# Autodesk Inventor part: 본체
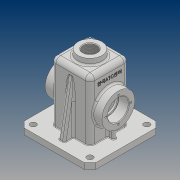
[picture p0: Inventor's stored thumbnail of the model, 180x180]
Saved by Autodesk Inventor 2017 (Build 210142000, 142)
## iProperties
Part Number: 본체
Material: 일반
Document SubType Name: Modeling
Designer: 20
Density: 1 g/cm^3
Appearance: 기본값
Author: 20
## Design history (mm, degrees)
sketch "스케치1"
  geometry: L1 (-32.5, -32.5)-(32.5, -32.5); L2 (32.5, -32.5)-(32.5, 32.5); L3 (32.5, 32.5)-(-32.5, 32.5); L4 (-32.5, 32.5)-(-32.5, -32.5); L5 (-32.5, -32.5)-(32.5, 32.5); L6 (32.5, -32.5)-(-32.5, 32.5); 1 further point
  constraints: 12 end point, 2 midpoint, 2 parallel, 1 horizontal, 1 perpendicular
  dimensions: "d0" = 65 distance of L3.end L2.end; "d1" = 65 distance of L2.end L1.end
extrude "돌출1" new body sketch "스케치1" distance "d2" = 110; taper "d3" = 0 deg
sketch "스케치2"
  geometry: L1 (27.5, 27.5)-(-27.5, 27.5); L2 (-27.5, 27.5)-(-27.5, -27.5); L3 (-27.5, -27.5)-(27.5, -27.5); L4 (27.5, -27.5)-(27.5, 27.5); L5 (27.5, 27.5)-(-27.5, -27.5); L6 (-27.5, 27.5)-(27.5, -27.5); 1 further point
  constraints: 12 end point, 2 midpoint, 2 parallel, 1 horizontal, 1 perpendicular
  dimensions: "d4" = 55 distance of L3.end L2.end; "d5" = 55 distance of L2.end L1.end
extrude "돌출2" cut sketch "스케치2" distance "d6" = 105; taper "d7" = 0 deg
sketch "스케치3"
  geometry: L1 (60, -60)-(-60, -60); L2 (-60, -60)-(-60, 60); L3 (-60, 60)-(60, 60); L4 (60, 60)-(60, -60); L5 (60, -60)-(-60, 60); L6 (-60, -60)-(60, 60); L7 (27.5, -27.5)-(-27.5, -27.5) reference; L8 (-27.5, -27.5)-(-27.5, 27.5) reference; L9 (-27.5, 27.5)-(27.5, 27.5) reference; L10 (27.5, 27.5)-(27.5, -27.5) reference; 1 further point
  constraints: 12 end point, 2 midpoint, 2 parallel, 1 horizontal, 1 perpendicular
  dimensions: "d8" = 120 distance of L2.end L3.end; "d9" = 120 distance of L1.end L2.end
extrude "돌출3" join sketch "스케치3" distance "d10" = 10; taper "d11" = 0 deg
sketch "스케치4"
  geometry: C1 r 20 at (0, 0); 1 further point
  constraints: 1 centre point, 1 coincident
  dimensions: "d12" = 40 diameter of C1
extrude "돌출4" join sketch "스케치4" distance "d13" = 10; taper "d14" = 0 deg
feature "면 기울기2" dims angle "d16" = 5 deg
sketch "스케치5"
  geometry: L1 (110, -27.5)-(110, 92.5) reference; C1 r 27.5 at (55, 32.5); 2 further points
  constraints: 1 centre point, 1 horizontal alignment, 1 midpoint
  dimensions: "d17" = 55 diameter of C1; "d92" = 55 distance from line of L1 C1.centre
extrude "돌출5" join sketch "스케치5" distance "d18" = 15; taper "d19" = 0 deg
sketch "스케치6"
  geometry: C1 r 27.5 at (0, 0) reference; C2 r 17.5 at (0, 0); 1 further point
  constraints: 1 centre point, 1 coincident
  dimensions: "d20" = 35 diameter of C2
extrude "돌출6" cut sketch "스케치6" distance "d21" = 17; taper "d22" = 0 deg
sketch "스케치7"
  geometry: C1 r 17.5 at (0, 0) reference; C2 r 15 at (0, 0); 1 further point
  constraints: 1 centre point, 1 coincident
  dimensions: "d23" = 30 diameter of C2
extrude "돌출7" cut sketch "스케치7" distance "d24" = 3; taper "d25" = 0 deg
fillet "모깎기3" dims "d28" = 3
fillet "모깎기4" dims "d29" = 3
sketch "스케치8" dims "d30" = 42
  geometry: C1 r 27.5 at (0, 0) reference; 3 further points
  constraints: 2 horizontal alignment, 1 coincident, 2 other
hole "구멍1" sketch "스케치8" at (-21, 0) diameter "d31" = 3.242; stored, may be unused: countersink angle "d35" = 90 deg, drill point angle "d37" = 118 deg; dims "d32" = 8, "d33" = 4, "d34" = 2, "d36" = 10
hole "구멍2" diameter "d43" = 22.835; stored, may be unused: countersink angle "d47" = 90 deg, drill point angle "d49" = 118 deg; dims "d41" = 10, "d42" = 10, "d44" = 50, "d45" = 4, "d46" = 2, "d48" = 15
sketch "스케치9"
  geometry: L1 (-60, 10)-(60, 10) reference; L2 (-42.5, 10)-(-42.5, 25); L3 (-27.5, 0)-(-27.5, 102) reference; 1 further point
  constraints: 2 end point, 1 point on line, 1 vertical
  dimensions: "d50" = 15 distance between parallel lines of L2 L3; "d51" = 15 distance of L2.start L2.end
feature "리브1" sketch "스케치9" dims "d52" = 1, "d53" = 6, "d54" = 0, "d55" = 0, "d56" = 1, "d57" = 1
sketch "스케치10"
  geometry: L1 (48, 10)-(37.42, 70); L2 (60, 0)-(60, 10) reference; L3 (60, 10)-(-60, 10) reference; 1 further point
  constraints: 2 end point, 1 point on line
  dimensions: "d58" = 10 deg angle of L2 L1; "d59" = 12 distance from line of L2 L1.start; "d60" = 60 vertical distance of L1.start L1.end
feature "리브2" sketch "스케치10" dims "d61" = 1, "d62" = 10, "d63" = 0, "d64" = 0, "d65" = 1, "d66" = 1
node "작업 평면1"
chamfer "모따기1" distance "d72" = 10; stored, may be unused: second distance "d73" = 2, angle "d74" = 45 deg
sketch "스케치12"
  geometry: C1 r 5 at (-47.5, -47.5); 1 further point
  constraints: 1 centre point
  dimensions: "d75" = 10 diameter of C1; "d76" = 47.5 horizontal distance of point (0, 0) C1.centre; "d77" = 47.5 horizontal distance of C1.centre point (0, 0)
extrude "돌출8" cut sketch "스케치12" stored distance "d78" = 10; taper "d79" = 0 deg
chamfer "모따기2" distance "d86" = 1; stored, may be unused: second distance "d87" = 2, angle "d88" = 45 deg
fillet "모깎기5" dims "d89" = 0.3
fillet "모깎기6" dims "d90" = 3
sketch "스케치13"
  geometry: L1 (-32.5, 10)-(-32.5, 110) reference; L2 (20, 120)-(-20, 120) reference; 2 further points
  constraints: 1 other
  dimensions: "d95" = 32.5 distance from line of point (0, 94) L1; "d96" = 26 distance from line of L2 point (0, 94)
feature "엠보싱2" sketch "스케치13" dims "d8" = 120, "d9" = 120, "d97" = 0.5, "d98" = 0
fillet "모깎기10" dims "d99" = 8
fillet "모깎기11" dims "d100" = 8
fillet "모깎기12" dims "d101" = 3
fillet "모깎기13" dims "d102" = 3
fillet "모깎기14" dims "d103" = 3
fillet "모깎기15" dims "d104" = 3
fillet "모깎기16" dims "d105" = 1
node "솔리드1"
pattern_circular "원형 패턴1" dims angle "d39" = 360 deg
mirror "미러1"
mirror "미러2"
mirror "미러3"
pattern_linear "직사각형 패턴1" dims "d82" = 95, "d85" = -95
